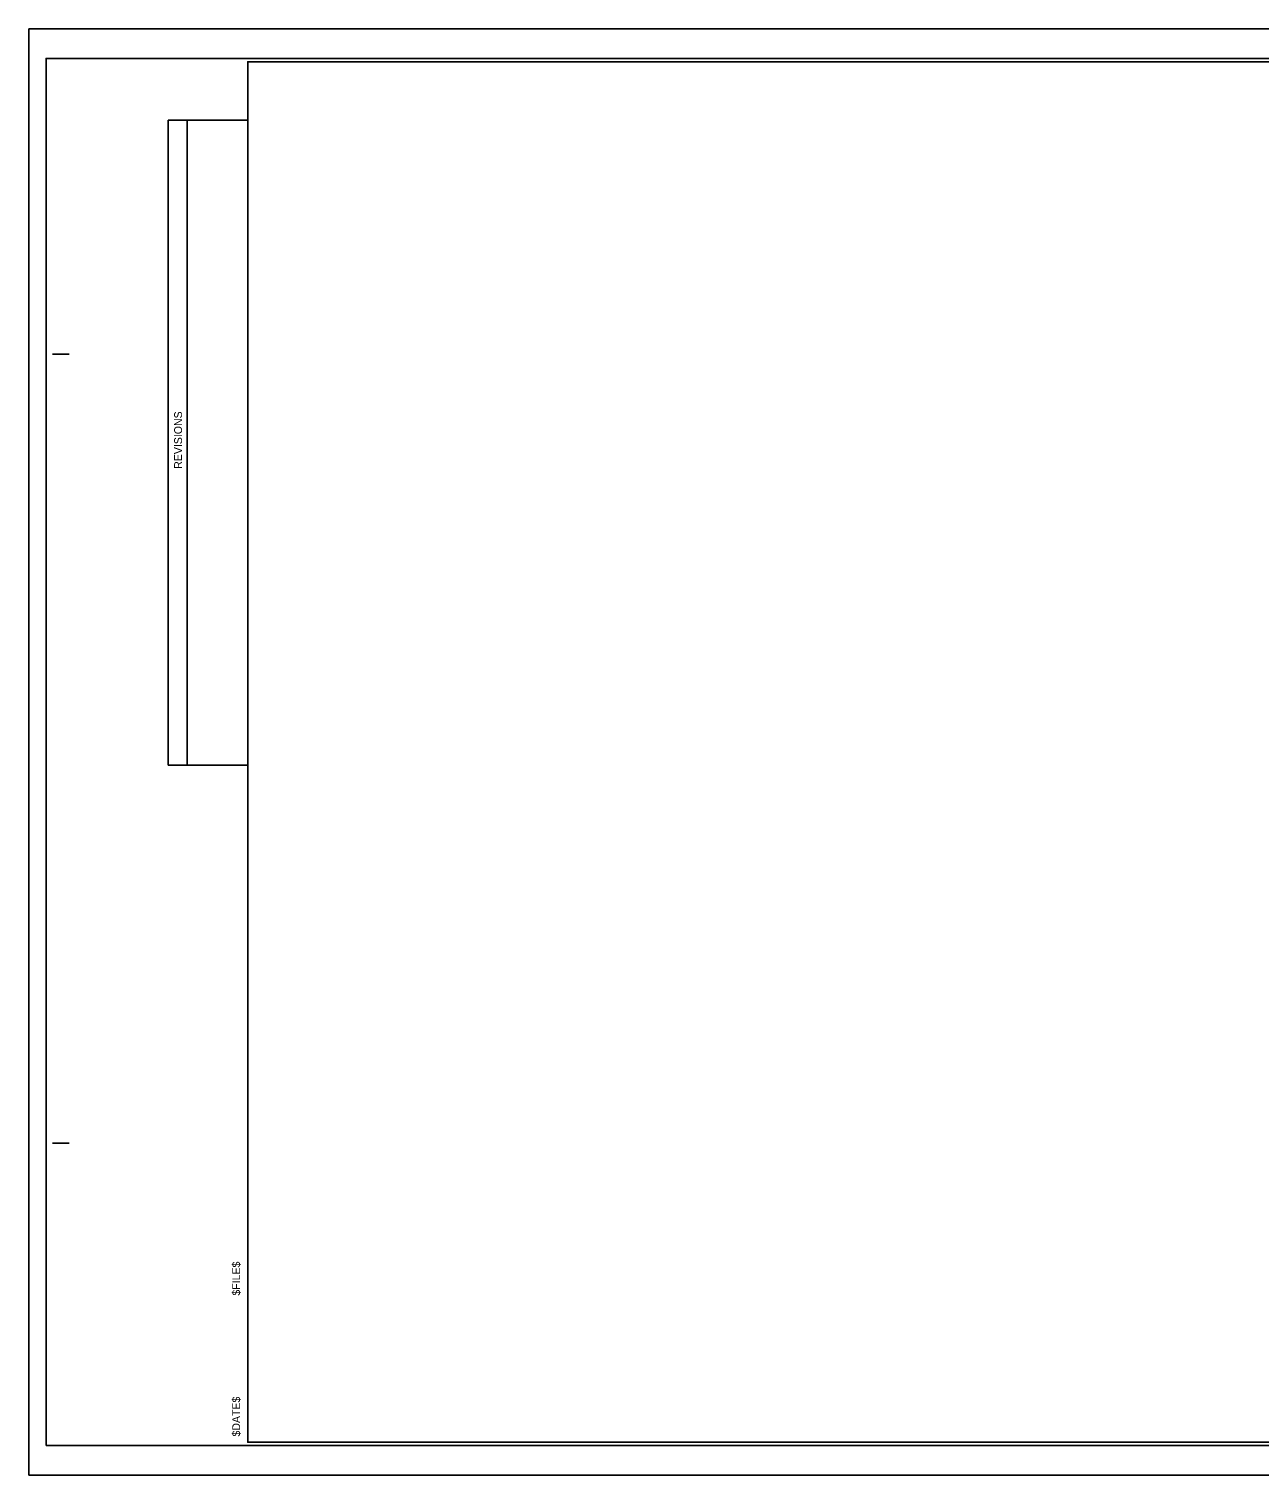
# Model space of a CAD drawing. Extents: x 2431000 to 2534000, y 645879 to 714000.
# Drawn here: x 2463853 to 2464789, y 676417 to 677517 of the extents above; entities that cross this region are included whole.
import ezdxf

# ---------------------------------------------------------------- set-up
doc = ezdxf.new("R2010")
doc.units = 0
for name, color, linetype in [('Old_Level_2', 7, 'Continuous'), ('Prop Dimension', 7, 'Continuous'), ('Prop Dimension Text', 7, 'Continuous'), ('Prop Shade Light', 7, 'Continuous'), ('Prop Terminator CELL', 7, 'Continuous')]:
    doc.layers.add(name, color=color, linetype=linetype)

msp = doc.modelspace()

# ---------------------------------------------------------------- linework, layer by layer
at = {"layer": 'Old_Level_2'}
for p, q in [((2463871.2, 677269.4), (2463883.7, 677269.4)), ((2463871.2, 676669.4), (2463883.7, 676669.4)), ((2464019.7, 676441.9), (2464019.7, 676441.9)), ((2464019.7, 676441.9), (2464019.7, 676441.9)), ((2464019.7, 676441.9), (2464019.7, 676441.9)), ((2464019.7, 676441.9), (2464019.7, 676441.9)), ((2464019.7, 676441.9), (2464019.7, 676441.9)), ((2464019.7, 676441.9), (2464019.7, 676441.9))]:
    msp.add_line(p, q, dxfattribs=at)
msp.add_lwpolyline([(2465519.7, 677491.9), (2464019.7, 677491.9), (2464019.7, 676441.9), (2465519.7, 676441.9)], close=True, dxfattribs=at)
msp.add_lwpolyline([(2464057.2, 676441.9), (2464057.2, 676441.9)], dxfattribs=at)
at = {"layer": 'Prop Dimension'}
msp.add_lwpolyline([(2463853.2, 676416.9), (2465536.7, 676416.9), (2465536.7, 677516.9), (2463853.2, 677516.9)], close=True, dxfattribs=at)
at = {"layer": 'Prop Shade Light'}
for p, q in [((2463959.2, 676956.9), (2463959.2, 677447.5)), ((2464019.7, 677447.5), (2463959.2, 677447.5)), ((2463973.7, 676956.9), (2463973.7, 677447.5)), ((2464019.7, 676956.9), (2463959.2, 676956.9))]:
    msp.add_line(p, q, dxfattribs=at)
at = {"layer": 'Prop Terminator CELL'}
msp.add_lwpolyline([(2463866.2, 676439.4), (2465532.2, 676439.4), (2465532.2, 677494.4), (2463866.2, 677494.4)], close=True, dxfattribs=at)

# ---------------------------------------------------------------- texts
at = {"layer": 'Prop Dimension Text'}
for s, p in [('$FILE$', (2464013.9, 676553.4)), ('$DATE$', (2464013.9, 676446.2))]:
    msp.add_text(s, height=6, rotation=90, dxfattribs=at).set_placement(p)
at = {"layer": 'Prop Shade Light'}
msp.add_text('REVISIONS', height=6, rotation=90, dxfattribs=at).set_placement((2463969.7, 677182.3))

doc.saveas('drawing.dxf')
